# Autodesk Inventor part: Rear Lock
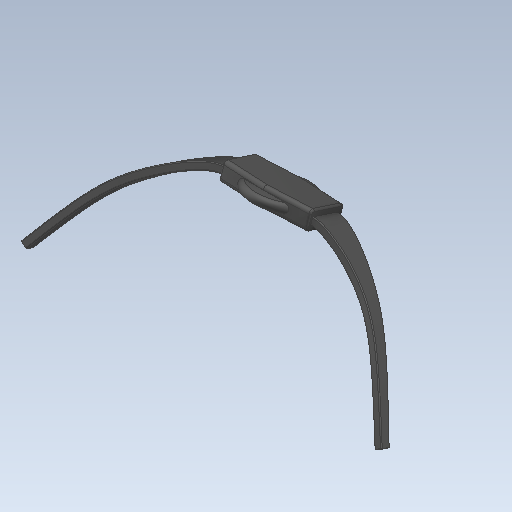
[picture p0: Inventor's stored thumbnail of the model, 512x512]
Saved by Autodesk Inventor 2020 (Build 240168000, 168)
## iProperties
Created: 2021-10
Part Number: Rear Lock
Material: Steel
Document SubType Name: Modeling
Designer: bruno
Density: 7.85 g/cm^3
Appearance: Par défaut
Author: bruno
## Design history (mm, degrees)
feature "Body2"
node "Solide1"
